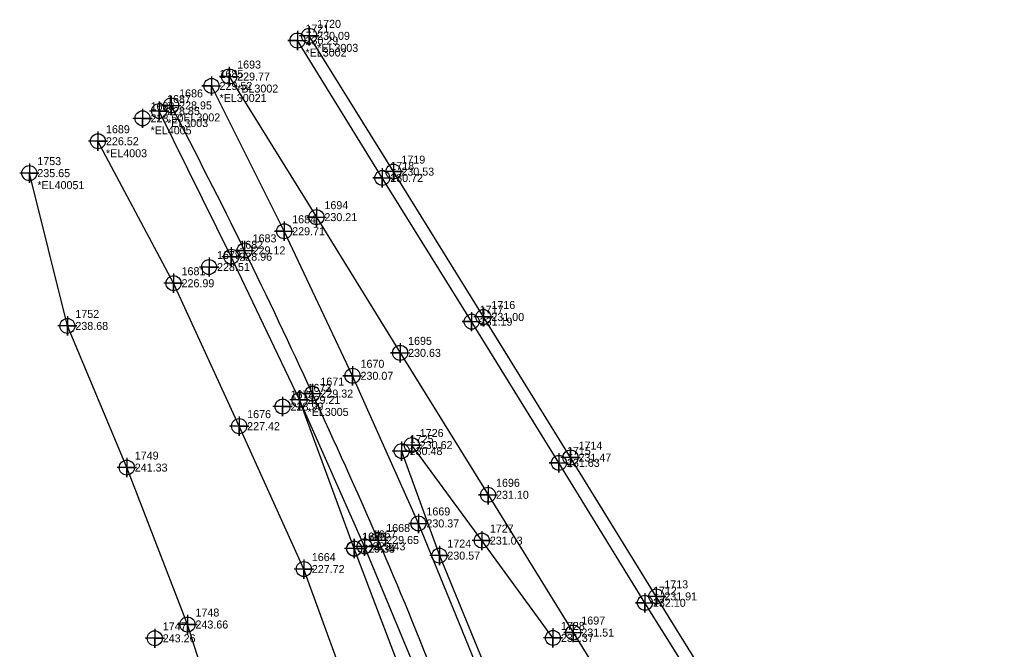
# Model space of a CAD drawing. Extents: x 2130962 to 2131465, y 643052 to 644206.
# Drawn here: x 2130961.8 to 2131269.8, y 644009.5 to 644206.1 of the extents above; entities that cross this region are included whole.
import ezdxf

# ---------------------------------------------------------------- set-up
doc = ezdxf.new("R2010")
doc.units = 0
for name, color, linetype in [('Exist DTM Breakline', 7, 'Continuous'), ('Exist DTM Breakline Cogo Comment', 7, 'Continuous'), ('Exist DTM Breakline Cogo Elevation', 7, 'Continuous'), ('Exist DTM Breakline Cogo Number', 7, 'Continuous'), ('Exist DTM Breakline Cogo Point CELL', 7, 'Continuous'), ('Exist DTM Drainline', 7, 'Continuous'), ('Exist DTM Drainline Cogo Comment', 7, 'Continuous'), ('Exist DTM Drainline Cogo Elevation', 7, 'Continuous'), ('Exist DTM Drainline Cogo Number', 7, 'Continuous'), ('Exist DTM Drainline Cogo Point CELL', 7, 'Continuous'), ('Exist DTM Regular Point CELL', 7, 'Continuous'), ('Exist DTM Regular Point Cogo Elevation', 7, 'Continuous'), ('Exist DTM Regular Point Cogo Number', 7, 'Continuous'), ('Exist Roads EOP', 7, 'Continuous'), ('Exist Roads EOP Other Cogo Comment', 7, 'Continuous'), ('Exist Roads EOP Other Cogo Elevation', 7, 'Continuous'), ('Exist Roads EOP Other Cogo Number', 7, 'Continuous'), ('Exist Roads EOP Other Cogo Point CELL', 7, 'Continuous'), ('Exist Roads EOT', 7, 'Continuous'), ('Exist Roads EOT Cogo Comment', 7, 'Continuous'), ('Exist Roads EOT Cogo Elevation', 7, 'Continuous'), ('Exist Roads EOT Cogo Number', 7, 'Continuous'), ('Exist Roads EOT Cogo Point CELL', 7, 'Continuous'), ('Exist Roads Soil', 7, 'Continuous'), ('Exist Roads Soil Cogo Comment', 7, 'Continuous'), ('Exist Roads Soil Cogo Elevation', 7, 'Continuous'), ('Exist Roads Soil Cogo Number', 7, 'Continuous'), ('Exist Roads Soil Cogo Point CELL', 7, 'Continuous')]:
    doc.layers.add(name, color=color, linetype=linetype)

msp = doc.modelspace()

# ---------------------------------------------------------------- linework, layer by layer
at = {"layer": 'Exist DTM Breakline'}
for points in [[(2131139.0887, 643604.6918), (2131124.996, 643650.6897), (2131108.0385, 643698.079), (2131093.5223, 643741.563), (2131079.9108, 643785.8518), (2131069.3516, 643834.7964), (2131058.0914, 643882.3322), (2131042.317, 643929.1682), (2131027.5453, 643975.0277), (2131014.156, 644017.233), (2130995.2084, 644066.2506), (2130976.662, 644110.4992), (2130964.7831, 644158.2254)], [(2131128.2786, 644013.0426), (2131106.0851, 644043.4387), (2131084.1956, 644073.293)], [(2131081.0395, 644071.409), (2131092.8041, 644038.758), (2131107.0869, 644004.0369), (2131110.421, 643995.4078)]]:
    msp.add_lwpolyline(points, dxfattribs=at)
at = {"layer": 'Exist DTM Breakline Cogo Point CELL'}
for points in [[(2131000.1314, 644178.3364), (2131000.1314, 644172.3364), (2131000.1314, 644175.3364), (2131003.1314, 644175.3364), (2130997.1314, 644175.3364)], [(2130964.7831, 644161.2254), (2130964.7831, 644155.2254), (2130964.7831, 644158.2254), (2130967.7831, 644158.2254), (2130961.7831, 644158.2254)], [(2131020.9057, 644131.8981), (2131020.9057, 644125.8981), (2131020.9057, 644128.8981), (2131023.9057, 644128.8981), (2131017.9057, 644128.8981)], [(2130976.662, 644113.4992), (2130976.662, 644107.4992), (2130976.662, 644110.4992), (2130979.662, 644110.4992), (2130973.662, 644110.4992)], [(2131043.8613, 644088.3061), (2131043.8613, 644082.3061), (2131043.8613, 644085.3061), (2131046.8613, 644085.3061), (2131040.8613, 644085.3061)], [(2131084.1956, 644076.293), (2131084.1956, 644070.293), (2131084.1956, 644073.293), (2131087.1956, 644073.293), (2131081.1956, 644073.293)], [(2131081.0395, 644074.409), (2131081.0395, 644068.409), (2131081.0395, 644071.409), (2131084.0395, 644071.409), (2131078.0395, 644071.409)], [(2130995.2084, 644069.2506), (2130995.2084, 644063.2506), (2130995.2084, 644066.2506), (2130998.2084, 644066.2506), (2130992.2084, 644066.2506)], [(2131106.0851, 644046.4387), (2131106.0851, 644040.4387), (2131106.0851, 644043.4387), (2131109.0851, 644043.4387), (2131103.0851, 644043.4387)], [(2131066.2525, 644043.9246), (2131066.2525, 644037.9246), (2131066.2525, 644040.9246), (2131069.2525, 644040.9246), (2131063.2525, 644040.9246)], [(2131092.8041, 644041.758), (2131092.8041, 644035.758), (2131092.8041, 644038.758), (2131095.8041, 644038.758), (2131089.8041, 644038.758)], [(2131014.156, 644020.233), (2131014.156, 644014.233), (2131014.156, 644017.233), (2131017.156, 644017.233), (2131011.156, 644017.233)], [(2131128.2786, 644016.0426), (2131128.2786, 644010.0426), (2131128.2786, 644013.0426), (2131131.2786, 644013.0426), (2131125.2786, 644013.0426)]]:
    msp.add_lwpolyline(points, dxfattribs=at)
for centre in [(2131000.1314, 644175.3364), (2130964.7831, 644158.2254), (2131020.9057, 644128.8981), (2130976.662, 644110.4992), (2131043.8613, 644085.3061), (2131081.0395, 644071.409), (2131084.1956, 644073.293), (2130995.2084, 644066.2506), (2131106.0851, 644043.4387), (2131066.2525, 644040.9246), (2131092.8041, 644038.758), (2131014.156, 644017.233), (2131128.2786, 644013.0426)]:
    msp.add_circle(centre, 2.344, dxfattribs=at)
at = {"layer": 'Exist DTM Drainline'}
msp.add_lwpolyline([(2131093.1541, 643926.3006), (2131087.2748, 643942.7791), (2131067.2265, 643988.5191), (2131050.4927, 644034.5509), (2131030.3027, 644079.1881), (2131009.8205, 644123.8359), (2130986.2155, 644168.1871)], dxfattribs=at)
at = {"layer": 'Exist DTM Drainline Cogo Point CELL'}
for points in [[(2130986.2155, 644171.1871), (2130986.2155, 644165.1871), (2130986.2155, 644168.1871), (2130989.2155, 644168.1871), (2130983.2155, 644168.1871)], [(2131009.8205, 644126.8359), (2131009.8205, 644120.8359), (2131009.8205, 644123.8359), (2131012.8205, 644123.8359), (2131006.8205, 644123.8359)], [(2131030.3027, 644082.1881), (2131030.3027, 644076.1881), (2131030.3027, 644079.1881), (2131033.3027, 644079.1881), (2131027.3027, 644079.1881)], [(2131050.4927, 644037.5509), (2131050.4927, 644031.5509), (2131050.4927, 644034.5509), (2131053.4927, 644034.5509), (2131047.4927, 644034.5509)]]:
    msp.add_lwpolyline(points, dxfattribs=at)
for centre in [(2130986.2155, 644168.1871), (2131009.8205, 644123.8359), (2131030.3027, 644079.1881), (2131050.4927, 644034.5509)]:
    msp.add_circle(centre, 2.344, dxfattribs=at)
at = {"layer": 'Exist DTM Regular Point CELL'}
msp.add_lwpolyline([(2131003.947, 644015.9225), (2131003.947, 644009.9225), (2131003.947, 644012.9225), (2131006.947, 644012.9225), (2131000.947, 644012.9225)], dxfattribs=at)
msp.add_circle((2131003.947, 644012.9225), 2.344, dxfattribs=at)
at = {"layer": 'Exist Roads EOP'}
for points in [[(2131269.8281, 643849.5438), (2131245.2333, 643889.3452), (2131216.1751, 643936.1301), (2131188.6585, 643980.6301), (2131160.5575, 644026.0233), (2131133.7706, 644069.3844), (2131106.5621, 644113.2921), (2131078.4587, 644158.6941), (2131052.1516, 644201.1049)], [(2131091.5349, 643988.0437), (2131088.176, 643996.5155), (2131069.4781, 644041.6508), (2131049.1592, 644087.3902), (2131027.8514, 644132.1094), (2131005.2923, 644177.6183)]]:
    msp.add_lwpolyline(points, dxfattribs=at)
at = {"layer": 'Exist Roads EOP Other Cogo Point CELL'}
for points in [[(2131052.1516, 644204.1049), (2131052.1516, 644198.1049), (2131052.1516, 644201.1049), (2131055.1516, 644201.1049), (2131049.1516, 644201.1049)], [(2131005.2923, 644180.6183), (2131005.2923, 644174.6183), (2131005.2923, 644177.6183), (2131008.2923, 644177.6183), (2131002.2923, 644177.6183)], [(2131078.4587, 644161.6941), (2131078.4587, 644155.6941), (2131078.4587, 644158.6941), (2131081.4587, 644158.6941), (2131075.4587, 644158.6941)], [(2131027.8514, 644135.1094), (2131027.8514, 644129.1094), (2131027.8514, 644132.1094), (2131030.8514, 644132.1094), (2131024.8514, 644132.1094)], [(2131106.5621, 644116.2921), (2131106.5621, 644110.2921), (2131106.5621, 644113.2921), (2131109.5621, 644113.2921), (2131103.5621, 644113.2921)], [(2131049.1592, 644090.3902), (2131049.1592, 644084.3902), (2131049.1592, 644087.3902), (2131052.1592, 644087.3902), (2131046.1592, 644087.3902)], [(2131133.7706, 644072.3844), (2131133.7706, 644066.3844), (2131133.7706, 644069.3844), (2131136.7706, 644069.3844), (2131130.7706, 644069.3844)], [(2131069.4781, 644044.6508), (2131069.4781, 644038.6508), (2131069.4781, 644041.6508), (2131072.4781, 644041.6508), (2131066.4781, 644041.6508)], [(2131160.5575, 644029.0233), (2131160.5575, 644023.0233), (2131160.5575, 644026.0233), (2131163.5575, 644026.0233), (2131157.5575, 644026.0233)]]:
    msp.add_lwpolyline(points, dxfattribs=at)
for centre in [(2131052.1516, 644201.1049), (2131005.2923, 644177.6183), (2131078.4587, 644158.6941), (2131027.8514, 644132.1094), (2131106.5621, 644113.2921), (2131049.1592, 644087.3902), (2131133.7706, 644069.3844), (2131069.4781, 644041.6508), (2131160.5575, 644026.0233)]:
    msp.add_circle(centre, 2.344, dxfattribs=at)
at = {"layer": 'Exist Roads EOT'}
for points in [[(2131266.2139, 643847.7337), (2131241.6557, 643887.3896), (2131212.415, 643934.4728), (2131185.0265, 643979.1763), (2131157.0131, 644024.017), (2131130.1473, 644067.7247), (2131102.8992, 644111.8313), (2131074.9921, 644156.7275), (2131048.5158, 644199.6357)], [(2131027.1782, 644188.3908), (2131054.4288, 644144.4752), (2131080.5567, 644102.0812), (2131108.007, 644057.7457), (2131134.6373, 644014.7205), (2131162.4421, 643969.638), (2131189.8746, 643925.4695), (2131217.6277, 643880.5724), (2131241.9317, 643841.1922)], [(2131255.7894, 643269.2666), (2131252.7511, 643319.2443), (2131249.9083, 643369.5477), (2131246.3502, 643419.1778), (2131242.1933, 643468.6938), (2131237.0867, 643518.9193), (2131230.8671, 643568.2588), (2131222.7066, 643619.1047), (2131213.6442, 643668.3078), (2131202.755, 643717.0933), (2131189.234, 643766.4577), (2131174.9499, 643814.1787), (2131159.2111, 643861.933), (2131141.9103, 643909.6722), (2131123.7008, 643956.0828), (2131104.9436, 644003.1503), (2131086.2706, 644048.8072), (2131065.6997, 644094.9191), (2131044.3618, 644140.0645), (2131021.6804, 644185.4526)]]:
    msp.add_lwpolyline(points, dxfattribs=at)
msp.add_spline([(2131166.718, 643215.2083), (2131172.3866, 643217.1804), (2131211.4056, 643247.1499), (2131223.758, 643268.7314), (2131228.3848, 643317.935), (2131225.533, 643367.8628), (2131222.2486, 643417.1873), (2131217.9619, 643466.6275), (2131212.8794, 643516.2377), (2131206.5633, 643565.5764), (2131198.9021, 643614.6757), (2131189.6851, 643663.4055), (2131179.3985, 643712.1311), (2131168.3085, 643760.7185), (2131155.755, 643808.9129), (2131141.6748, 643856.5528), (2131126.5354, 643904.2758), (2131110.3559, 643951.0191), (2131092.4533, 643998.1348), (2131073.722, 644043.631), (2131053.1654, 644089.359), (2131032.0052, 644134.0908), (2131009.0644, 644179.3802)], degree=3, dxfattribs=at)
at = {"layer": 'Exist Roads EOT Cogo Point CELL'}
for points in [[(2131048.5158, 644202.6357), (2131048.5158, 644196.6357), (2131048.5158, 644199.6357), (2131045.5158, 644199.6357), (2131051.5158, 644199.6357)], [(2131027.1782, 644191.3908), (2131027.1782, 644185.3908), (2131027.1782, 644188.3908), (2131024.1782, 644188.3908), (2131030.1782, 644188.3908)], [(2131021.6804, 644188.4526), (2131021.6804, 644182.4526), (2131021.6804, 644185.4526), (2131018.6804, 644185.4526), (2131024.6804, 644185.4526)], [(2131009.0644, 644182.3802), (2131009.0644, 644176.3802), (2131009.0644, 644179.3802), (2131006.0644, 644179.3802), (2131012.0644, 644179.3802)], [(2131074.9921, 644159.7275), (2131074.9921, 644153.7275), (2131074.9921, 644156.7275), (2131071.9921, 644156.7275), (2131077.9921, 644156.7275)], [(2131054.4288, 644147.4752), (2131054.4288, 644141.4752), (2131054.4288, 644144.4752), (2131051.4288, 644144.4752), (2131057.4288, 644144.4752)], [(2131044.3618, 644143.0645), (2131044.3618, 644137.0645), (2131044.3618, 644140.0645), (2131041.3618, 644140.0645), (2131047.3618, 644140.0645)], [(2131032.0052, 644137.0908), (2131032.0052, 644131.0908), (2131032.0052, 644134.0908), (2131029.0052, 644134.0908), (2131035.0052, 644134.0908)], [(2131102.8992, 644114.8313), (2131102.8992, 644108.8313), (2131102.8992, 644111.8313), (2131099.8992, 644111.8313), (2131105.8992, 644111.8313)], [(2131080.5567, 644105.0812), (2131080.5567, 644099.0812), (2131080.5567, 644102.0812), (2131077.5567, 644102.0812), (2131083.5567, 644102.0812)], [(2131065.6997, 644097.9191), (2131065.6997, 644091.9191), (2131065.6997, 644094.9191), (2131062.6997, 644094.9191), (2131068.6997, 644094.9191)], [(2131053.1654, 644092.359), (2131053.1654, 644086.359), (2131053.1654, 644089.359), (2131050.1654, 644089.359), (2131056.1654, 644089.359)], [(2131130.1473, 644070.7247), (2131130.1473, 644064.7247), (2131130.1473, 644067.7247), (2131127.1473, 644067.7247), (2131133.1473, 644067.7247)], [(2131108.007, 644060.7457), (2131108.007, 644054.7457), (2131108.007, 644057.7457), (2131105.007, 644057.7457), (2131111.007, 644057.7457)], [(2131086.2706, 644051.8072), (2131086.2706, 644045.8072), (2131086.2706, 644048.8072), (2131083.2706, 644048.8072), (2131089.2706, 644048.8072)], [(2131073.722, 644046.631), (2131073.722, 644040.631), (2131073.722, 644043.631), (2131070.722, 644043.631), (2131076.722, 644043.631)], [(2131157.0131, 644027.017), (2131157.0131, 644021.017), (2131157.0131, 644024.017), (2131154.0131, 644024.017), (2131160.0131, 644024.017)], [(2131134.6373, 644017.7205), (2131134.6373, 644011.7205), (2131134.6373, 644014.7205), (2131131.6373, 644014.7205), (2131137.6373, 644014.7205)]]:
    msp.add_lwpolyline(points, dxfattribs=at)
for centre in [(2131048.5158, 644199.6357), (2131027.1782, 644188.3908), (2131021.6804, 644185.4526), (2131009.0644, 644179.3802), (2131074.9921, 644156.7275), (2131054.4288, 644144.4752), (2131044.3618, 644140.0645), (2131032.0052, 644134.0908), (2131102.8992, 644111.8313), (2131080.5567, 644102.0812), (2131065.6997, 644094.9191), (2131053.1654, 644089.359), (2131130.1473, 644067.7247), (2131108.007, 644057.7457), (2131086.2706, 644048.8072), (2131073.722, 644043.631), (2131157.0131, 644024.017), (2131134.6373, 644014.7205)]:
    msp.add_circle(centre, 2.344, dxfattribs=at)
at = {"layer": 'Exist Roads Soil'}
msp.add_lwpolyline([(2131224.8674, 643317.753), (2131220.141, 643317.6487), (2131216.7544, 643367.544), (2131211.084, 643416.163), (2131207.4344, 643466.363), (2131202.1097, 643514.7948), (2131195.0195, 643564.3052), (2131187.2605, 643612.6498), (2131179.506, 643660.9545), (2131164.8317, 643709.0781), (2131153.9175, 643755.9834), (2131140.8896, 643804.492), (2131127.2512, 643851.9231), (2131113.4771, 643899.8082), (2131083.6685, 643994.997), (2131066.191, 644040.9476), (2131049.1539, 644087.3869)], dxfattribs=at)
at = {"layer": 'Exist Roads Soil Cogo Point CELL'}
for points in [[(2131049.1539, 644084.3869), (2131049.1539, 644090.3869), (2131049.1539, 644087.3869), (2131052.1539, 644087.3869), (2131046.1539, 644087.3869)], [(2131066.191, 644037.9476), (2131066.191, 644043.9476), (2131066.191, 644040.9476), (2131069.191, 644040.9476), (2131063.191, 644040.9476)]]:
    msp.add_lwpolyline(points, dxfattribs=at)
for centre in [(2131049.1539, 644087.3869), (2131066.191, 644040.9476)]:
    msp.add_circle(centre, 2.344, dxfattribs=at)

# ---------------------------------------------------------------- texts
at = {"layer": 'Exist DTM Breakline Cogo Comment'}
for s, p in [('*EL4005', (2131002.6314, 644170.3364)), ('*EL40051', (2130967.2831, 644153.2254))]:
    msp.add_text(s, height=2.5, dxfattribs=at).set_placement(p)
at = {"layer": 'Exist DTM Breakline Cogo Elevation'}
for s, p in [('228.50', (2131002.6314, 644174.0864)), ('235.65', (2130967.2831, 644156.9754)), ('228.51', (2131023.4057, 644127.6481)), ('238.68', (2130979.162, 644109.2492)), ('228.99', (2131046.3613, 644084.0561)), ('230.62', (2131086.6956, 644072.043)), ('230.48', (2131083.5395, 644070.159)), ('241.33', (2130997.7084, 644065.0006)), ('229.34', (2131068.7525, 644039.6746)), ('231.03', (2131108.5851, 644042.1887)), ('230.57', (2131095.3041, 644037.508)), ('243.66', (2131016.656, 644015.983)), ('231.37', (2131130.7786, 644011.7926))]:
    msp.add_text(s, height=2.5, dxfattribs=at).set_placement(p)
at = {"layer": 'Exist DTM Breakline Cogo Number'}
for s, p in [('1688', (2131002.6314, 644177.8364)), ('1753', (2130967.2831, 644160.7254)), ('1679', (2131023.4057, 644131.3981)), ('1752', (2130979.162, 644112.9992)), ('1678', (2131046.3613, 644087.8061)), ('1725', (2131083.5395, 644073.909)), ('1726', (2131086.6956, 644075.793)), ('1749', (2130997.7084, 644068.7506)), ('1727', (2131108.5851, 644045.9387)), ('1675', (2131068.7525, 644043.4246)), ('1724', (2131095.3041, 644041.258)), ('1748', (2131016.656, 644019.733)), ('1728', (2131130.7786, 644015.5426))]:
    msp.add_text(s, height=2.5, dxfattribs=at).set_placement(p)
at = {"layer": 'Exist DTM Drainline Cogo Comment'}
msp.add_text('*EL4003', height=2.5, dxfattribs=at).set_placement((2130988.7155, 644163.1871))
at = {"layer": 'Exist DTM Drainline Cogo Elevation'}
for s, p in [('226.52', (2130988.7155, 644166.9371)), ('226.99', (2131012.3205, 644122.5859)), ('227.42', (2131032.8027, 644077.9381)), ('227.72', (2131052.9927, 644033.3009))]:
    msp.add_text(s, height=2.5, dxfattribs=at).set_placement(p)
at = {"layer": 'Exist DTM Drainline Cogo Number'}
for s, p in [('1689', (2130988.7155, 644170.6871)), ('1681', (2131012.3205, 644126.3359)), ('1676', (2131032.8027, 644081.6881)), ('1664', (2131052.9927, 644037.0509))]:
    msp.add_text(s, height=2.5, dxfattribs=at).set_placement(p)
at = {"layer": 'Exist DTM Regular Point Cogo Elevation'}
msp.add_text('243.26', height=2.5, dxfattribs=at).set_placement((2131006.447, 644011.6725))
at = {"layer": 'Exist DTM Regular Point Cogo Number'}
msp.add_text('1747', height=2.5, dxfattribs=at).set_placement((2131006.447, 644015.4225))
at = {"layer": 'Exist Roads EOP Other Cogo Comment'}
for p in [(2131054.6516, 644196.1049), (2131007.7923, 644172.6183)]:
    msp.add_text('*EL3003', height=2.5, dxfattribs=at).set_placement(p)
at = {"layer": 'Exist Roads EOP Other Cogo Elevation'}
for s, p in [('230.09', (2131054.6516, 644199.8549)), ('228.85', (2131007.7923, 644176.3683)), ('230.53', (2131080.9587, 644157.4441)), ('228.96', (2131030.3514, 644130.8594)), ('231.00', (2131109.0621, 644112.0421)), ('229.21', (2131051.6592, 644086.1402)), ('231.47', (2131136.2706, 644068.1344)), ('229.43', (2131071.9781, 644040.4008)), ('231.91', (2131163.0575, 644024.7733))]:
    msp.add_text(s, height=2.5, dxfattribs=at).set_placement(p)
at = {"layer": 'Exist Roads EOP Other Cogo Number'}
for s, p in [('1720', (2131054.6516, 644203.6049)), ('1687', (2131007.7923, 644180.1183)), ('1719', (2131080.9587, 644161.1941)), ('1682', (2131030.3514, 644134.6094)), ('1716', (2131109.0621, 644115.7921)), ('1672', (2131051.6592, 644089.8902)), ('1714', (2131136.2706, 644071.8844)), ('1667', (2131071.9781, 644044.1508)), ('1713', (2131163.0575, 644028.5233))]:
    msp.add_text(s, height=2.5, dxfattribs=at).set_placement(p)
at = {"layer": 'Exist Roads EOT Cogo Comment'}
for s, p in [('*EL3002', (2131051.0158, 644194.6357)), ('*BL3002', (2131029.6782, 644183.3908)), ('*EL30021', (2131024.1804, 644180.4526)), ('*EL3002', (2131011.5644, 644174.3802))]:
    msp.add_text(s, height=2.5, dxfattribs=at).set_placement(p)
at = {"layer": 'Exist Roads EOT Cogo Elevation'}
for s, p in [('230.29', (2131051.0158, 644198.3857)), ('229.77', (2131029.6782, 644187.1408)), ('229.52', (2131024.1804, 644184.2026)), ('228.95', (2131011.5644, 644178.1302)), ('230.72', (2131077.4921, 644155.4775)), ('230.21', (2131056.9288, 644143.2252)), ('229.71', (2131046.8618, 644138.8145)), ('229.12', (2131034.5052, 644132.8408)), ('231.19', (2131105.3992, 644110.5813)), ('230.63', (2131083.0567, 644100.8312)), ('230.07', (2131068.1997, 644093.6691)), ('229.32', (2131055.6654, 644088.109)), ('231.63', (2131132.6473, 644066.4747)), ('231.10', (2131110.507, 644056.4957)), ('230.37', (2131088.7706, 644047.5572)), ('229.65', (2131076.222, 644042.381)), ('232.10', (2131159.5131, 644022.767)), ('231.51', (2131137.1373, 644013.4705))]:
    msp.add_text(s, height=2.5, dxfattribs=at).set_placement(p)
at = {"layer": 'Exist Roads EOT Cogo Number'}
for s, p in [('1721', (2131051.0158, 644202.1357)), ('1693', (2131029.6782, 644190.8908)), ('1685', (2131024.1804, 644187.9526)), ('1686', (2131011.5644, 644181.8802)), ('1718', (2131077.4921, 644159.2275)), ('1694', (2131056.9288, 644146.9752)), ('1684', (2131046.8618, 644142.5645)), ('1683', (2131034.5052, 644136.5908)), ('1717', (2131105.3992, 644114.3313)), ('1695', (2131083.0567, 644104.5812)), ('1670', (2131068.1997, 644097.4191)), ('1671', (2131055.6654, 644091.859)), ('1715', (2131132.6473, 644070.2247)), ('1696', (2131110.507, 644060.2457)), ('1669', (2131088.7706, 644051.3072)), ('1668', (2131076.222, 644046.131)), ('1712', (2131159.5131, 644026.517)), ('1697', (2131137.1373, 644017.2205))]:
    msp.add_text(s, height=2.5, dxfattribs=at).set_placement(p)
at = {"layer": 'Exist Roads Soil Cogo Comment'}
msp.add_text('*EL3005', height=2.5, dxfattribs=at).set_placement((2131051.6539, 644082.3869))
at = {"layer": 'Exist Roads Soil Cogo Elevation'}
for s, p in [('229.21', (2131051.6539, 644086.1369)), ('229.35', (2131068.691, 644039.6976))]:
    msp.add_text(s, height=2.5, dxfattribs=at).set_placement(p)
at = {"layer": 'Exist Roads Soil Cogo Number'}
for s, p in [('1673', (2131051.6539, 644089.8869)), ('1666', (2131068.691, 644043.4476))]:
    msp.add_text(s, height=2.5, dxfattribs=at).set_placement(p)

doc.saveas('drawing.dxf')
